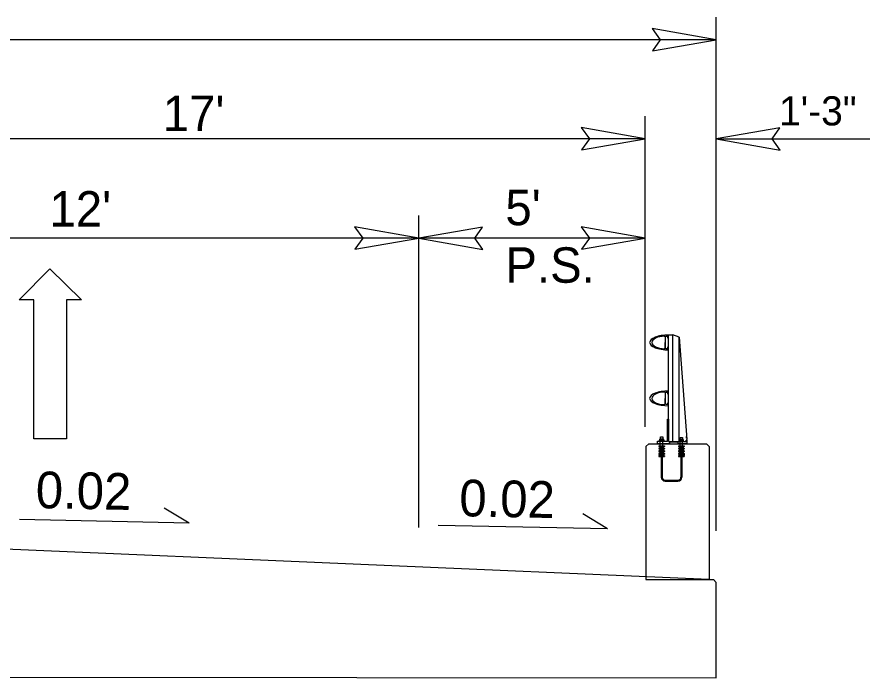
# Model space of a CAD drawing. Extents: x 1733676 to 1734289, y 540979 to 541226.
# Drawn here: x 1733995.74 to 1734010.8, y 541126.52 to 541138.18 of the extents above; entities that cross this region are included whole.
import ezdxf

# ---------------------------------------------------------------- set-up
doc = ezdxf.new("R2010")
doc.units = 0
for name, color, linetype in [('Prop Dimension', 7, 'Continuous'), ('Prop Lane Arrow CELL', 7, 'Continuous'), ('Prop Terminator CELL', 7, 'Continuous'), ('Typical Bridge Rail Two Bar CELL', 7, 'Continuous'), ('Typical Pavement Slope CELL', 7, 'Continuous'), ('Typical Pavement Slope Information CELL', 7, 'Continuous'), ('Typical Slope Point Local CELL', 7, 'Continuous')]:
    doc.layers.add(name, color=color, linetype=linetype)

msp = doc.modelspace()

# ---------------------------------------------------------------- linework, layer by layer
at = {"layer": 'Prop Dimension'}
for p, q in [((1734008.084, 541129.122), (1734008.084, 541138.185)), ((1734008.084, 541137.785), (1733963.084, 541137.785)), ((1734006.834, 541130.955), (1734006.834, 541136.435)), ((1734006.834, 541136.035), (1733990.834, 541136.035)), ((1734008.084, 541136.035), (1734010.8, 541136.035)), ((1734002.834, 541129.179), (1734002.834, 541134.685)), ((1734002.834, 541134.285), (1733990.834, 541134.285)), ((1734006.834, 541134.285), (1734002.834, 541134.285))]:
    msp.add_line(p, q, dxfattribs=at)
at = {"layer": 'Prop Lane Arrow CELL'}
for p, q in [((1733995.778, 541133.193), (1733996.321, 541133.744)), ((1733996.321, 541133.744), (1733996.881, 541133.193)), ((1733996.041, 541133.193), (1733995.778, 541133.193)), ((1733996.041, 541130.743), (1733996.041, 541133.193)), ((1733996.881, 541133.193), (1733996.618, 541133.193)), ((1733996.618, 541133.193), (1733996.618, 541130.743)), ((1733996.618, 541130.743), (1733996.041, 541130.743))]:
    msp.add_line(p, q, dxfattribs=at)
at = {"layer": 'Prop Terminator CELL'}
for points in [[(1734006.959, 541137.591), (1734008.084, 541137.785), (1734006.953, 541137.985), (1734007.097, 541137.785)], [(1734005.709, 541135.841), (1734006.834, 541136.035), (1734005.703, 541136.235), (1734005.847, 541136.035)], [(1734009.209, 541136.229), (1734008.084, 541136.035), (1734009.216, 541135.835), (1734009.072, 541136.035)], [(1734001.709, 541134.091), (1734002.834, 541134.285), (1734001.703, 541134.485), (1734001.847, 541134.285)], [(1734003.959, 541134.479), (1734002.834, 541134.285), (1734003.966, 541134.085), (1734003.822, 541134.285)], [(1734005.709, 541134.091), (1734006.834, 541134.285), (1734005.703, 541134.485), (1734005.847, 541134.285)]]:
    msp.add_lwpolyline(points, close=True, dxfattribs=at)
at = {"layer": 'Typical Bridge Rail Two Bar CELL'}
for p, q in [((1734007.182, 541132.545), (1734007.182, 541132.443)), ((1734007.245, 541132.577), (1734007.32, 541132.577)), ((1734007.245, 541130.693), (1734007.245, 541132.577)), ((1734007.434, 541132.539), (1734007.32, 541132.577)), ((1734007.32, 541130.693), (1734007.32, 541132.577)), ((1734007.434, 541130.693), (1734007.434, 541132.539)), ((1734007.434, 541132.539), (1734007.566, 541130.731)), ((1734007.182, 541132.341), (1734007.182, 541132.443)), ((1734007.434, 541131.675), (1734007.438, 541131.675)), ((1734007.182, 541131.558), (1734007.182, 541131.456)), ((1734007.182, 541131.354), (1734007.182, 541131.456)), ((1734007.099, 541130.619), (1734007.099, 541130.703)), ((1734007.1, 541130.744), (1734007.1, 541130.779)), ((1734007.1, 541130.779), (1734007.144, 541130.779)), ((1734007.144, 541130.779), (1734007.144, 541130.744)), ((1734007.146, 541130.619), (1734007.146, 541130.703)), ((1734007.449, 541130.734), (1734007.449, 541130.769)), ((1734007.449, 541130.769), (1734007.492, 541130.769)), ((1734007.492, 541130.769), (1734007.492, 541130.734)), ((1734007.562, 541130.752), (1734007.562, 541130.785)), ((1734007.566, 541130.693), (1734007.566, 541130.731)), ((1734006.895, 541130.655), (1734006.846, 541130.607)), ((1734006.846, 541130.607), (1734006.846, 541128.262)), ((1734006.895, 541130.655), (1734007.916, 541130.655)), ((1734007.074, 541130.619), (1734007.174, 541130.619)), ((1734007.074, 541130.608), (1734007.174, 541130.608)), ((1734007.074, 541130.575), (1734007.115, 541130.575)), ((1734007.074, 541130.564), (1734007.115, 541130.564)), ((1734007.096, 541130.597), (1734007.115, 541130.597)), ((1734007.096, 541130.586), (1734007.115, 541130.586)), ((1734007.096, 541130.552), (1734007.115, 541130.552)), ((1734007.115, 541130.597), (1734007.132, 541130.597)), ((1734007.115, 541130.597), (1734007.115, 541130.066)), ((1734007.132, 541130.597), (1734007.151, 541130.597)), ((1734007.132, 541130.597), (1734007.132, 541130.066)), ((1734007.132, 541130.586), (1734007.151, 541130.586)), ((1734007.132, 541130.575), (1734007.174, 541130.575)), ((1734007.132, 541130.564), (1734007.174, 541130.564)), ((1734007.132, 541130.552), (1734007.151, 541130.552)), ((1734007.422, 541130.619), (1734007.522, 541130.619)), ((1734007.422, 541130.608), (1734007.522, 541130.608)), ((1734007.422, 541130.575), (1734007.464, 541130.575)), ((1734007.422, 541130.564), (1734007.464, 541130.564)), ((1734007.444, 541130.597), (1734007.464, 541130.597)), ((1734007.444, 541130.586), (1734007.464, 541130.586)), ((1734007.444, 541130.552), (1734007.464, 541130.552)), ((1734007.45, 541130.61), (1734007.45, 541130.693)), ((1734007.464, 541130.597), (1734007.481, 541130.597)), ((1734007.464, 541130.597), (1734007.464, 541130.066)), ((1734007.481, 541130.597), (1734007.5, 541130.597)), ((1734007.481, 541130.597), (1734007.481, 541130.066)), ((1734007.481, 541130.586), (1734007.5, 541130.586)), ((1734007.481, 541130.575), (1734007.522, 541130.575)), ((1734007.481, 541130.564), (1734007.522, 541130.564)), ((1734007.481, 541130.552), (1734007.5, 541130.552)), ((1734007.493, 541130.61), (1734007.493, 541130.693)), ((1734007.964, 541130.607), (1734007.916, 541130.655)), ((1734007.964, 541130.607), (1734007.964, 541128.262)), ((1734007.074, 541130.53), (1734007.115, 541130.53)), ((1734007.074, 541130.519), (1734007.115, 541130.519)), ((1734007.074, 541130.486), (1734007.115, 541130.486)), ((1734007.074, 541130.475), (1734007.115, 541130.475)), ((1734007.074, 541130.442), (1734007.115, 541130.442)), ((1734007.074, 541130.431), (1734007.115, 541130.431)), ((1734007.096, 541130.541), (1734007.115, 541130.541)), ((1734007.096, 541130.508), (1734007.115, 541130.508)), ((1734007.096, 541130.497), (1734007.115, 541130.497)), ((1734007.096, 541130.464), (1734007.115, 541130.464)), ((1734007.096, 541130.453), (1734007.115, 541130.453)), ((1734007.132, 541130.541), (1734007.151, 541130.541)), ((1734007.132, 541130.53), (1734007.174, 541130.53)), ((1734007.132, 541130.519), (1734007.174, 541130.519)), ((1734007.132, 541130.508), (1734007.151, 541130.508)), ((1734007.132, 541130.497), (1734007.151, 541130.497)), ((1734007.132, 541130.486), (1734007.174, 541130.486)), ((1734007.132, 541130.475), (1734007.174, 541130.475)), ((1734007.132, 541130.464), (1734007.151, 541130.464)), ((1734007.132, 541130.453), (1734007.151, 541130.453)), ((1734007.132, 541130.442), (1734007.174, 541130.442)), ((1734007.132, 541130.431), (1734007.174, 541130.431)), ((1734007.422, 541130.53), (1734007.464, 541130.53)), ((1734007.422, 541130.519), (1734007.464, 541130.519)), ((1734007.422, 541130.486), (1734007.464, 541130.486)), ((1734007.422, 541130.475), (1734007.464, 541130.475)), ((1734007.422, 541130.442), (1734007.464, 541130.442)), ((1734007.422, 541130.431), (1734007.464, 541130.431)), ((1734007.444, 541130.541), (1734007.464, 541130.541)), ((1734007.444, 541130.508), (1734007.464, 541130.508)), ((1734007.444, 541130.497), (1734007.464, 541130.497)), ((1734007.444, 541130.464), (1734007.464, 541130.464)), ((1734007.444, 541130.453), (1734007.464, 541130.453)), ((1734007.481, 541130.541), (1734007.5, 541130.541)), ((1734007.481, 541130.53), (1734007.522, 541130.53)), ((1734007.481, 541130.519), (1734007.522, 541130.519)), ((1734007.481, 541130.508), (1734007.5, 541130.508)), ((1734007.481, 541130.497), (1734007.5, 541130.497)), ((1734007.481, 541130.486), (1734007.522, 541130.486)), ((1734007.481, 541130.475), (1734007.522, 541130.475)), ((1734007.481, 541130.464), (1734007.5, 541130.464)), ((1734007.481, 541130.453), (1734007.5, 541130.453)), ((1734007.481, 541130.442), (1734007.522, 541130.442)), ((1734007.481, 541130.431), (1734007.522, 541130.431)), ((1734007.185, 541130.013), (1734007.41, 541130.013)), ((1734007.185, 541129.997), (1734007.41, 541129.997)), ((1734006.846, 541128.262), (1734007.955, 541128.262)), ((1734007.955, 541128.262), (1734008.036, 541128.262)), ((1734008.084, 541128.208), (1734008.036, 541128.262))]:
    msp.add_line(p, q, dxfattribs=at)
for points in [[(1734007.245, 541132.313), (1734007.245, 541132.362), (1734007.225, 541132.362), (1734007.225, 541132.353), (1734007.227, 541132.353), (1734007.227, 541132.333), (1734007.194, 541132.333), (1734007.19, 541132.364), (1734007.19, 541132.443), (1734007.19, 541132.522), (1734007.194, 541132.553), (1734007.227, 541132.553), (1734007.227, 541132.533), (1734007.225, 541132.533), (1734007.225, 541132.525), (1734007.245, 541132.525), (1734007.245, 541132.574)], [(1734007.245, 541131.325), (1734007.245, 541131.374), (1734007.225, 541131.374), (1734007.225, 541131.366), (1734007.227, 541131.366), (1734007.227, 541131.346), (1734007.194, 541131.346), (1734007.19, 541131.377), (1734007.19, 541131.456), (1734007.19, 541131.535), (1734007.194, 541131.566), (1734007.227, 541131.566), (1734007.227, 541131.546), (1734007.225, 541131.546), (1734007.225, 541131.538), (1734007.245, 541131.538), (1734007.245, 541131.586)], [(1734007.052, 541130.655), (1734007.052, 541130.703), (1734007.226, 541130.703), (1734007.226, 541131.089), (1734007.245, 541131.089), (1734007.245, 541130.693), (1734007.557, 541130.693), (1734007.557, 541130.721), (1734007.566, 541130.721), (1734007.566, 541130.655), (1734007.415, 541130.655), (1734007.415, 541130.682), (1734007.264, 541130.682), (1734007.264, 541130.655), (1734007.052, 541130.655)], [(1734007.078, 541130.702), (1734007.078, 541130.711), (1734007.122, 541130.711), (1734007.165, 541130.711), (1734007.165, 541130.702)], [(1734007.09, 541130.711), (1734007.09, 541130.738), (1734007.095, 541130.743), (1734007.149, 541130.743), (1734007.154, 541130.738), (1734007.154, 541130.711), (1734007.09, 541130.711), (1734007.112, 541130.711), (1734007.112, 541130.738), (1734007.106, 541130.743), (1734007.112, 541130.738), (1734007.117, 541130.743), (1734007.128, 541130.743), (1734007.133, 541130.738), (1734007.133, 541130.711), (1734007.133, 541130.738), (1734007.138, 541130.743)], [(1734007.428, 541130.693), (1734007.428, 541130.701), (1734007.471, 541130.701), (1734007.514, 541130.701), (1734007.514, 541130.693)], [(1734007.439, 541130.701), (1734007.439, 541130.728), (1734007.445, 541130.734), (1734007.497, 541130.734), (1734007.503, 541130.728), (1734007.503, 541130.701), (1734007.439, 541130.701), (1734007.46, 541130.701), (1734007.46, 541130.728), (1734007.455, 541130.734), (1734007.46, 541130.728), (1734007.465, 541130.734), (1734007.476, 541130.734), (1734007.482, 541130.728), (1734007.482, 541130.701), (1734007.482, 541130.728), (1734007.487, 541130.734)], [(1734007.073, 541130.619), (1734007.073, 541130.608), (1734007.096, 541130.597), (1734007.096, 541130.586), (1734007.073, 541130.575), (1734007.073, 541130.564), (1734007.096, 541130.552), (1734007.096, 541130.541), (1734007.073, 541130.53), (1734007.073, 541130.519), (1734007.096, 541130.508), (1734007.096, 541130.497), (1734007.073, 541130.486), (1734007.073, 541130.475), (1734007.096, 541130.464), (1734007.096, 541130.453), (1734007.073, 541130.442), (1734007.073, 541130.431)], [(1734007.174, 541130.619), (1734007.174, 541130.608), (1734007.151, 541130.597), (1734007.151, 541130.586), (1734007.174, 541130.575), (1734007.174, 541130.564), (1734007.151, 541130.552), (1734007.151, 541130.541), (1734007.174, 541130.53), (1734007.174, 541130.519), (1734007.151, 541130.508), (1734007.151, 541130.497), (1734007.174, 541130.486), (1734007.174, 541130.475), (1734007.151, 541130.464), (1734007.151, 541130.453), (1734007.174, 541130.442), (1734007.174, 541130.431)], [(1734007.422, 541130.619), (1734007.422, 541130.608), (1734007.444, 541130.597), (1734007.444, 541130.586), (1734007.422, 541130.575), (1734007.422, 541130.564), (1734007.444, 541130.552), (1734007.444, 541130.541), (1734007.422, 541130.53), (1734007.422, 541130.519), (1734007.444, 541130.508), (1734007.444, 541130.497), (1734007.422, 541130.486), (1734007.422, 541130.475), (1734007.444, 541130.464), (1734007.444, 541130.453), (1734007.422, 541130.442), (1734007.422, 541130.431)], [(1734007.522, 541130.619), (1734007.522, 541130.608), (1734007.5, 541130.597), (1734007.5, 541130.586), (1734007.522, 541130.575), (1734007.522, 541130.564), (1734007.5, 541130.552), (1734007.5, 541130.541), (1734007.522, 541130.53), (1734007.522, 541130.519), (1734007.5, 541130.508), (1734007.5, 541130.497), (1734007.522, 541130.486), (1734007.522, 541130.475), (1734007.5, 541130.464), (1734007.5, 541130.453), (1734007.522, 541130.442), (1734007.522, 541130.431)]]:
    msp.add_lwpolyline(points, dxfattribs=at)
for centre in [(1734007.082, 541130.458), (1734007.513, 541130.458)]:
    msp.add_circle(centre, 0.00834, dxfattribs=at)
for centre, radius, start, end in [((1734007.174, 541132.545), 0.00783, 0, 90), ((1734007.174, 541132.341), 0.00783, 270, 0), ((1734007.174, 541131.558), 0.00783, 0, 90), ((1734007.174, 541131.354), 0.00783, 270, 0), ((1734007.185, 541130.066), 0.07, 180, 270), ((1734007.185, 541130.066), 0.0534, 180, 270), ((1734007.41, 541130.066), 0.0534, 270, 0), ((1734007.41, 541130.066), 0.07, 270, 0)]:
    msp.add_arc(centre, radius, start, end, dxfattribs=at)
for centre, major_axis, ratio, start_param, end_param in [((1734007.245, 541132.443), (-0.334, 0), 0.39036, 4.712404, 6.283584), ((1734007.174, 541132.443), (-0.222, 0), 0.495501, 4.712489, 6.283652), ((1734007.245, 541132.443), (-0.334, 0), 0.39036, 0.000398, 1.570782), ((1734007.174, 541132.443), (-0.222, 0), 0.495501, 0.000467, 1.570696), ((1734007.245, 541131.456), (-0.334, 0), 0.39036, 4.712404, 6.283584), ((1734007.245, 541131.456), (-0.334, 0), 0.39036, 0.000398, 1.570782), ((1734007.174, 541131.456), (-0.222, 0), 0.495501, 4.712489, 6.283652), ((1734007.174, 541131.456), (-0.222, 0), 0.495501, 0.000467, 1.570696)]:
    msp.add_ellipse(centre, major_axis=major_axis, ratio=ratio, start_param=start_param, end_param=end_param, dxfattribs=at)
at = {"layer": 'Typical Pavement Slope CELL'}
msp.add_line((1734007.955, 541128.262), (1733990.834, 541129.001), dxfattribs=at)
at = {"layer": 'Typical Pavement Slope Information CELL'}
for p, q in [((1733998.78, 541129.257), (1733998.343, 541129.522)), ((1734006.168, 541129.154), (1734005.73, 541129.419)), ((1733998.78, 541129.257), (1733995.789, 541129.317)), ((1734006.168, 541129.154), (1734003.177, 541129.214))]:
    msp.add_line(p, q, dxfattribs=at)
at = {"layer": 'Typical Slope Point Local CELL'}
for p, q in [((1734008.084, 541126.524), (1734008.084, 541128.208)), ((1733963.096, 541126.563), (1734008.084, 541126.524))]:
    msp.add_line(p, q, dxfattribs=at)

# ---------------------------------------------------------------- texts
at = {"layer": 'Typical Pavement Slope Information CELL'}
for p in [(1733996.069, 541129.521), (1734003.546, 541129.378)]:
    msp.add_text('0.02', height=0.6476, rotation=358.8543, dxfattribs=at).set_placement(p)
at = {"layer": 'Typical Slope Point Local CELL'}
for s, height, p in [("17'", 0.6249, (1733998.316, 541136.174)), ('1\'-3"', 0.5141, (1734009.196, 541136.273)), ("12'", 0.6249, (1733996.316, 541134.488)), ("5'", 0.6249, (1734004.364, 541134.512)), ('P.S.', 0.6249, (1734004.364, 541133.497))]:
    msp.add_text(s, height=height, rotation=360, dxfattribs=at).set_placement(p)

doc.saveas('drawing.dxf')
